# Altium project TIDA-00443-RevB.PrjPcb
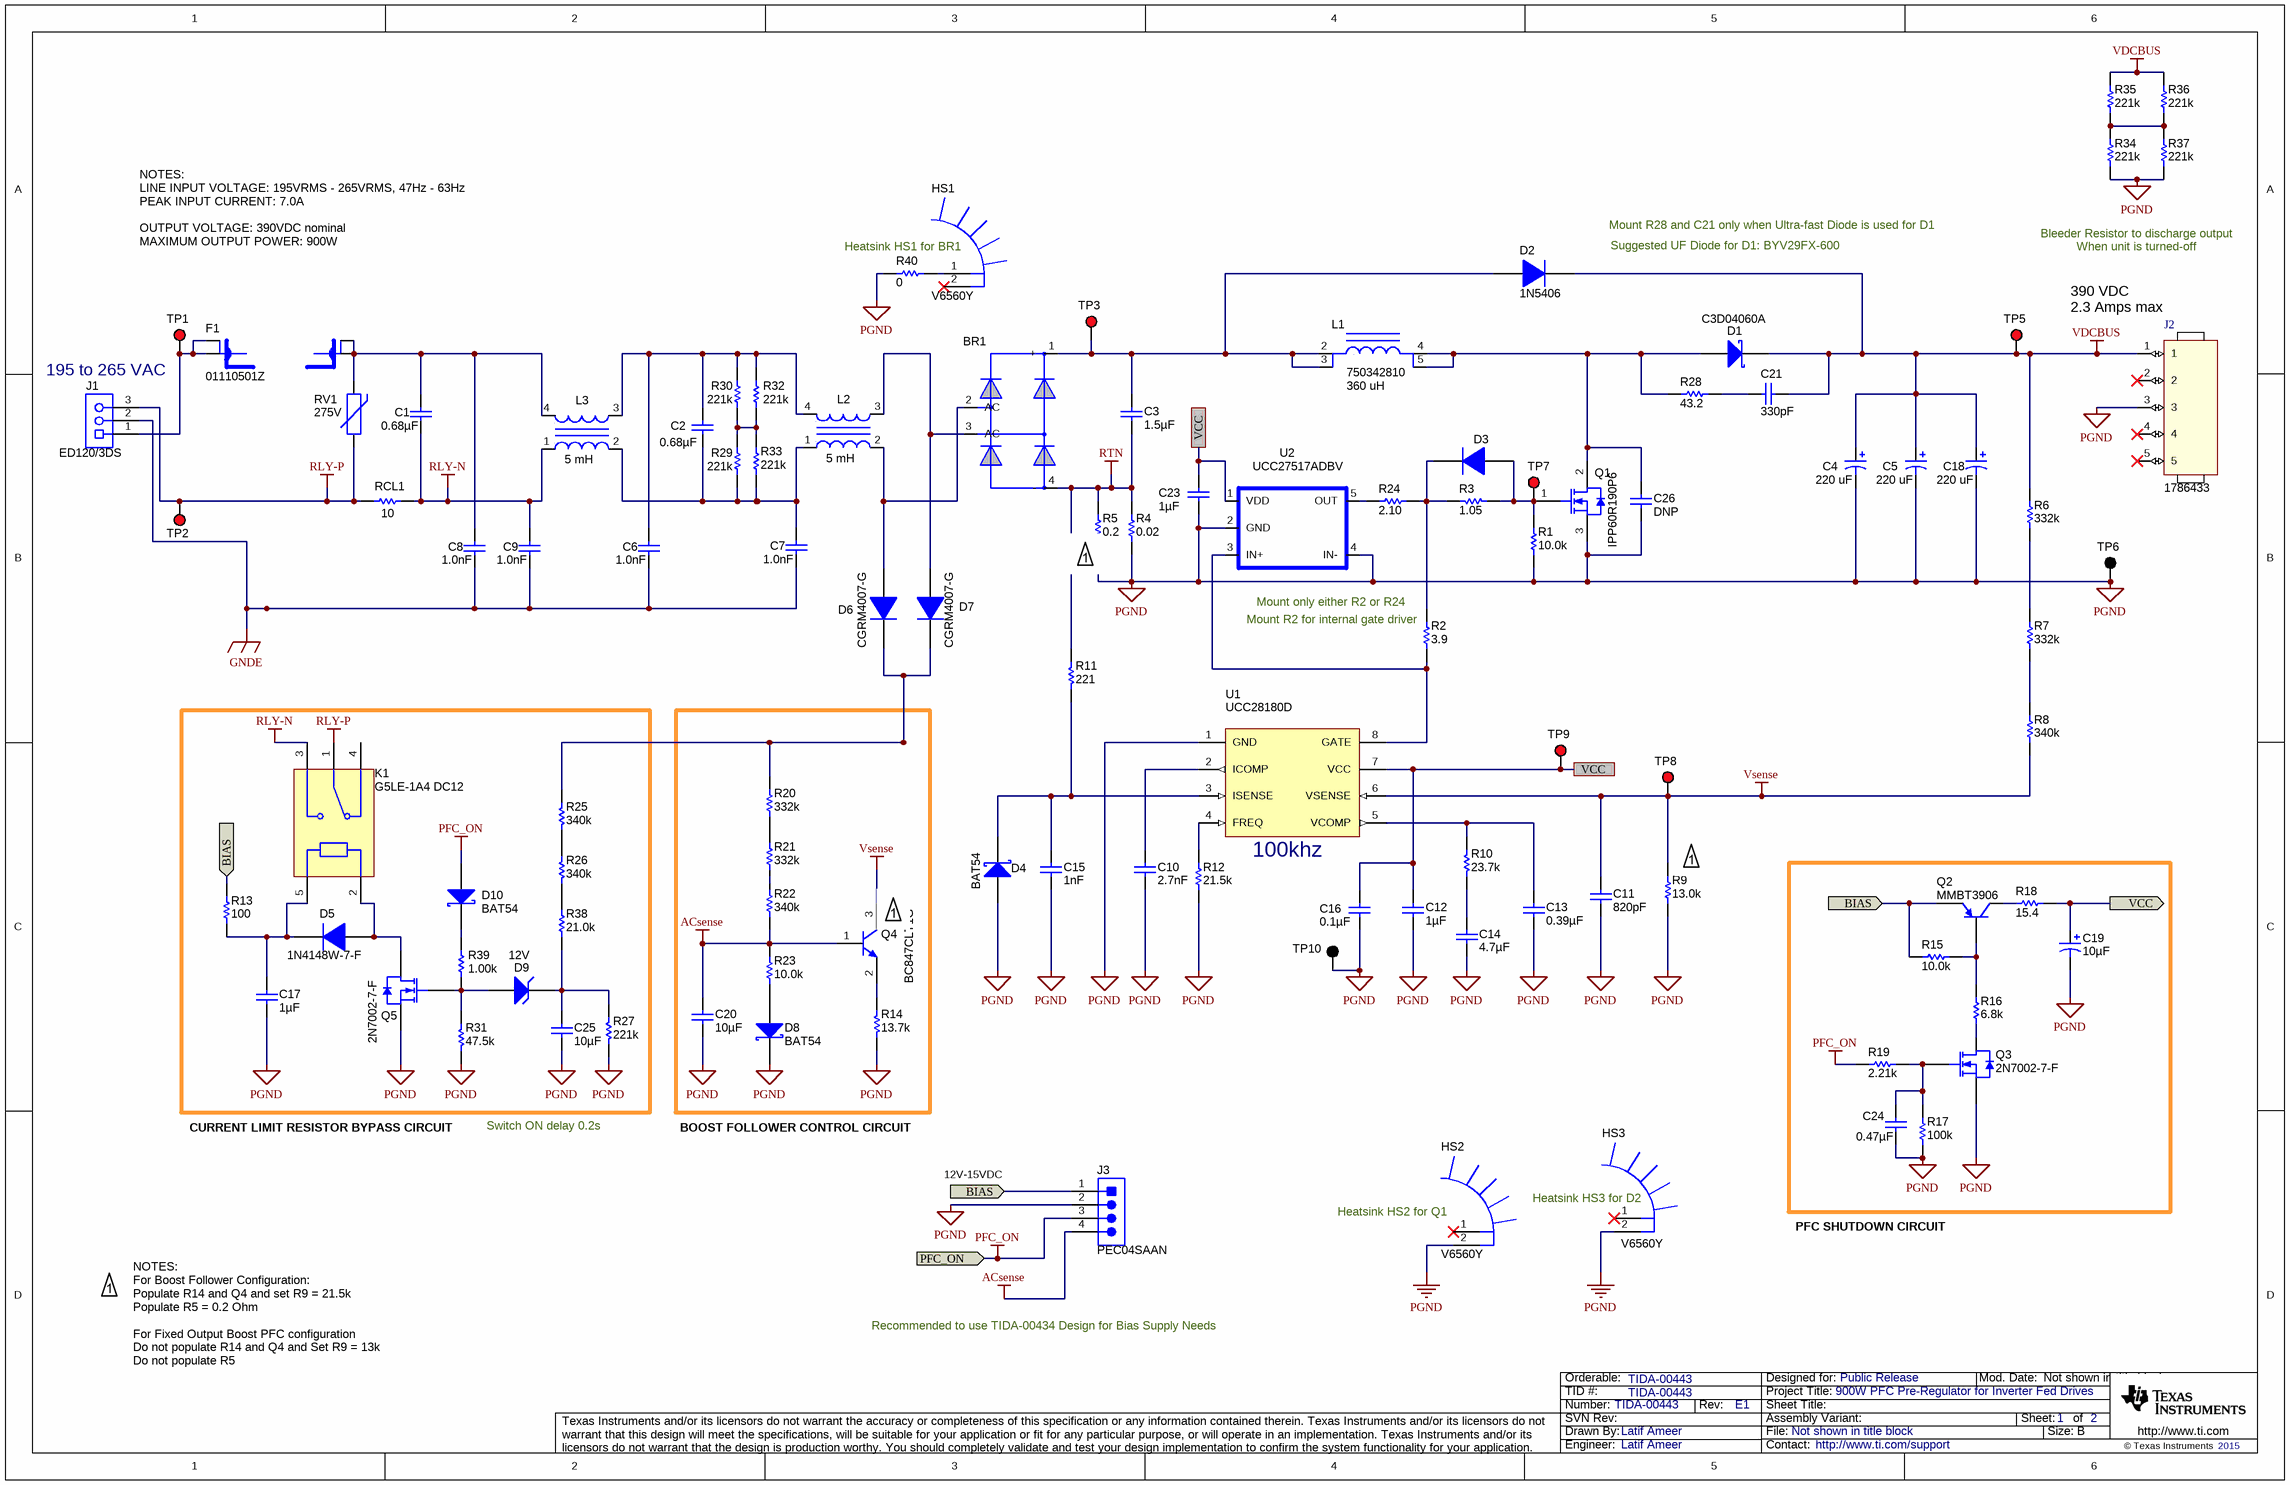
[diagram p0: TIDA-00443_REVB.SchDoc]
CopyrightYear: 2015; EVM_Orderable: TIDA-00443; PCB_Layout: Avinash; PCB_Rev: E2; PRJ_Customer: Public Release; PRJ_Engineer: Latif Ameer; PRJ_Number: TIDA-00443; PRJ_Title: 900W PFC Pre-Regulator for Inverter Fed Drives; SCH_Rev: E1; TechSupport: http://www.ti.com/support; TID: TIDA-00443
2 sheets, 124 parts. Net scope: flat (ports and power ports of the same name join across sheets).
Board file: TIDA-00443-RevB.PcbDoc
Sheets:
  TIDA-00443_REVB.SchDoc
  TID_Hardware.SchDoc

## Sheet TIDA-00443_REVB.SchDoc
size 431 x 279 mm; Date: 27-Mar-2015; ApprovedBy: Not shown in title block; CheckedBy: Salil Chellappan; Author: Latif Ameer; CompanyName: Texas Instruments India Pvt. Ltd; DrawnBy: Latif Ameer; Engineer: Latif Ameer; Organization: Not shown in title block; Address1: Not shown in title block; Address2: Not shown in title block; Address3: Not shown in title block; Address4: Not shown in title block; DocumentNumber: TIDA-00443-RevA; Revision: A; SheetNumber: 1; SheetTotal: 2; PageSetup: Record=PageOptions¦CenterHorizontal=True¦CenterVertical=True¦PrintScale=0.64¦XCorrection=1.00¦YCorrection=1.00¦PrintKind=0¦BorderSize=5000000¦LeftOffset=0¦BottomOffset=0¦Orientation=2¦PaperLength=1000¦PaperWidth=1000¦Scale=100¦PaperSource=15¦PrintQuality=-3¦MediaType=1¦DitherType=10¦PrintScaleMode=1¦PaperKind=Letter¦PaperIndex=1

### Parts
BR1  GBJ1508-BP  [BRIDGE-TSIL_PKG]  (value not drawn)
C1  ValueDisplayed: 0.68µF  [B32923_16.5mm_10.5]  (hidden comment: B32923C3684M)
C2  ValueDisplayed: 0.68µF  [B32923_16.5mm_10.5]  (hidden comment: B32923C3684M)
C3  ValueDisplayed: 1.5µF  [B32923_22mm]  (hidden comment: B32923C3155M)
C4  value 220 uF  [CAPPRD750W80D1800H5200]  (hidden comment: 450QXW220MEFC18X50)
C5  value 220 uF  [CAPPRD750W80D1800H5200]  (hidden comment: 450QXW220MEFC18X50)
C6  1.0nF  [CAPRD750W60D1050H1450]
C7  1.0nF  [CAPRD750W60D1050H1450]
C8  1.0nF  [CAPRD750W60D1050H1450]
C9  1.0nF  [CAPRD750W60D1050H1450]
C10  ValueDisplayed: 2.7nF  [0603]  (hidden comment: 06031C272JAT2A)
C11  ValueDisplayed: 820pF  [0603]  (hidden comment: C0603C821K5RACTU)
C12  ValueDisplayed: 1µF  [0603]  (hidden comment: C1608X7R1E105K080AB)
C13  ValueDisplayed: 0.39µF  [0603]  (hidden comment: C0603C394K4RACTU)
C14  ValueDisplayed: 4.7µF  [0603]  (hidden comment: GRM188R61C475KAAJ)
C15  ValueDisplayed: 1nF  [0603]  (hidden comment: 06031C102KAT2A)
C16  ValueDisplayed: 0.1µF  [0603]  (hidden comment: 06035C104KAT2A)
C17  ValueDisplayed: 1µF  [0603]  (hidden comment: C1608X7R1E105K080AB)
C18  value 220 uF  [CAPPRD750W80D1800H5200]  (hidden comment: 450QXW220MEFC18X50)
C19  ValueDisplayed: 10µF  [PW_500x700]  (hidden comment: UPW1V100MDD6)
C20  ValueDisplayed: 10µF  [0805_HV]  (hidden comment: C2012X5R1E106K125AB)
C21  ValueDisplayed: 330pF  [1206]  (hidden comment: GRM31A7U3A331JW31D)
C23  ValueDisplayed: 1µF  [0603]  (hidden comment: C1608X7R1E105K080AB)
C24  ValueDisplayed: 0.47µF  [0603]  (hidden comment: C0603C474K4RACTU)
C25  ValueDisplayed: 10µF  [1206]  (hidden comment: UMK316BBJ106ML-T)
C26  ValueDisplayed: DNP  [1206]  (hidden comment: GRM31A7U3A101JW31D)
D1  C3D04060A  [TO-220-F2]
D2  1N5406  [DO-201AD]
D3  MMDL914-TP  [sod-323]  (value not drawn)
D4  Alternate PartNumber: BAT54  [sod-323]  (hidden comment: BAT54HT1G)
D5  1N4148W-7-F  [SOD-123]
D6  CGRM4007-G  [MINI-SMA]
D7  CGRM4007-G  [MINI-SMA]
D8  Alternate PartNumber: BAT54  [sod-323]  (hidden comment: BAT54HT1G)
D9  value 12V  [sod-323]  (hidden comment: BZX384-C12,115)
D10  Alternate PartNumber: BAT54  [sod-323]  (hidden comment: BAT54HT1G)
F1  01110501Z  [LITTELFUSE_01110501Z]
HS1  V6560Y  [HS_ASS_0595]
HS2  V6560Y  [HS_ASS_0595]
HS3  V6560Y  [HS_ASS_0595]
J1  ED120/3DS  [CONN_ED120_3DS]
J2  1786433  [PHOENIX_1786433]
J3  PEC04SAAN  [SULLINS_PEC04SAAN]
K1  G5LE-1A4 DC12  [RELAY_G5LA-1]
L1  750342810  value 360 uH  [WE_750342810]
L2  5 mH  [IND_8113-RC]
L3  5 mH  [IND_8113-RC]
Q1  IPP60R190P6
Q2  MMBT3906  [SOT-23]
Q3  2N7002-7-F  [SOT-23]
Q4  BC847CLT1G  [SOT-23]
Q5  2N7002-7-F  [SOT-23]
R1  ValueDisplayed: 10.0k  [0603]  (hidden comment: CRCW060310K0FKEA)
R2  ValueDisplayed: 3.9  [1206]  (hidden comment: CRCW12063R90JNEA)
R3  ValueDisplayed: 1.05  [1206]  (hidden comment: CRCW12061R05FKEA)
R4  ValueDisplayed: 0.02  [2512]  (hidden comment: CRA2512-FZ-R020ELF)
R5  ValueDisplayed: 0.2  [2512]  (hidden comment: CRM2512-JW-201ELF)
R6  ValueDisplayed: 332k  [1206]  (hidden comment: CRCW1206332KFKEA)
R7  ValueDisplayed: 332k  [1206]  (hidden comment: CRCW1206332KFKEA)
R8  ValueDisplayed: 340k  [1206]  (hidden comment: CRCW1206340KFKEA)
R9  ValueDisplayed: 13.0k  [0603]  (hidden comment: CRCW060313K0FKEA)
R10  ValueDisplayed: 23.7k  [0603]  (hidden comment: CRCW060323K7FKEA)
R11  value 221  [0603M]  (hidden comment: CRCW0603221RFKEA)
R12  ValueDisplayed: 21.5k  [0603]  (hidden comment: CRCW060321K5FKEA)
R13  ValueDisplayed: 100  [1206]  (hidden comment: CRCW1206100RFKEA)
R14  ValueDisplayed: 13.7k  [0603]  (hidden comment: CRCW060313K7FKEA)
R15  value 10.0k  [0603]  (hidden comment: CRCW060310K0FKEA)
R16  ValueDisplayed: 6.8k  [0603]  (hidden comment: CRCW06036K80JNEA)
R17  ValueDisplayed: 100k  [0603]  (hidden comment: CRCW0603100KFKEA)
R18  ValueDisplayed: 15.4  [0603]  (hidden comment: CRCW060315R4FKEA)
R19  ValueDisplayed: 2.21k  [0603]  (hidden comment: CRCW06032K21FKEA)
R20  ValueDisplayed: 332k  [1206]  (hidden comment: CRCW1206332KFKEA)
R21  ValueDisplayed: 332k  [1206]  (hidden comment: CRCW1206332KFKEA)
R22  ValueDisplayed: 340k  [1206]  (hidden comment: CRCW1206340KFKEA)
R23  ValueDisplayed: 10.0k  [0603]  (hidden comment: CRCW060310K0FKEA)
R24  ValueDisplayed: 2.10  [1206]  (hidden comment: CRCW12062R10FKEA)
R25  ValueDisplayed: 340k  [1206]  (hidden comment: CRCW1206340KFKEA)
R26  ValueDisplayed: 340k  [1206]  (hidden comment: CRCW1206340KFKEA)
R27  ValueDisplayed: 221k  [0603]  (hidden comment: CRCW0603221KFKEA)
R28  ValueDisplayed: 43.2  [2512]  (hidden comment: CRM2512-FX-43R2ELF)
R29  ValueDisplayed: 221k  [1206]  (hidden comment: CRCW1206221KFKEA)
R30  ValueDisplayed: 221k  [1206]  (hidden comment: CRCW1206221KFKEA)
R31  ValueDisplayed: 47.5k  [0603]  (hidden comment: CRCW060347K5FKEA)
R32  ValueDisplayed: 221k  [1206]  (hidden comment: CRCW1206221KFKEA)
R33  ValueDisplayed: 221k  [1206]  (hidden comment: CRCW1206221KFKEA)
R34  ValueDisplayed: 221k  [1206]  (hidden comment: CRCW1206221KFKEA)
R35  ValueDisplayed: 221k  [1206]  (hidden comment: CRCW1206221KFKEA)
R36  ValueDisplayed: 221k  [1206]  (hidden comment: CRCW1206221KFKEA)
R37  ValueDisplayed: 221k  [1206]  (hidden comment: CRCW1206221KFKEA)
R38  ValueDisplayed: 21.0k  [1206]  (hidden comment: CRCW120621K0FKEA)
R39  ValueDisplayed: 1.00k  [0603]  (hidden comment: CRCW06031K00FKEA)
R40  ValueDisplayed: 0  [0805_HV]  (hidden comment: CRCW08050000Z0EA)
RCL1  ValueDisplayed: 10  [RESADV550W80L2600D750B]  (hidden comment: AC07000002009JAC00)
RV1  value 275V  [VAR_S10K275E2]  (hidden comment: S10K275E2)
TP1  5000  [Keystone5000]  (value not drawn)
TP2  5000  [Keystone5000]  (value not drawn)
TP3  5000  [Keystone5000]  (value not drawn)
TP5  5000  [Keystone5000]  (value not drawn)
TP6  5001  [Keystone5001]  (value not drawn)
TP7  5000  [Keystone5000]  (value not drawn)
TP8  5000  [Keystone5000]  (value not drawn)
TP9  5000  [Keystone5000]  (value not drawn)
TP10  5001  [Keystone5001]  (value not drawn)
U1  UCC28180D  [D0008A_N]
U2  UCC27517ADBV  [DBV0005A_N]

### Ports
BIAS, PFC_ON (in), VCC

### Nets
ACsense: C20.1 J3.4 Q4.1(B) R22.1 R23.1
GNDE: C6.2 C7.2 C8.2 C9.2 J1.2
PFC_ON: D10.2(A) J3.3 R19.1 ; port PFC_ON
PGND: C4.2(-) C5.2(-) C10.2 C11.2 C12.2 C13.1 C14.2 C15.1 C16.2 C17.2 C18.2(-) C19.2(-) C20.2 C23.2 C24.2 C25.2 C26.2 D4.2(A) D8.1(K) HS2.2 HS3.2 J2.3 J3.2 Q1.3(S) Q3.2(S) Q5.2(S) R1.2 R4.1 R5.1 R9.1 R12.2 R14.2 R17.1 R27.1 R31.1 R34.1 R37.1 R40.1 TP6.1 TP10.1 U1.1(GND) U2.2(GND) U2.4(IN-)
RLY-N: C1.2 C9.1 K1.3 L3.1 RCL1.2
RLY-P: J1.3 K1.1 RCL1.1 RV1.1 TP2.1
RTN: BR1.4(-) C3.2 R4.2 R5.2 R11.1
VDCBUS: C4.1(+) C5.1(+) C18.1(+) C21.1 D1.1(K) D2.1(K) J2.1 R6.2 R35.2 R36.2 TP5.1
Vsense: C11.1 Q4.3(C) R8.1 R9.2 TP8.1 U1.6(VSENSE)
BIAS: J3.1 Q2.2(E) R13.1 R15.1 ; port BIAS
VCC: C12.1 C16.1 C19.1(+) C23.1 R18.2 TP9.1 U1.7(VCC) U2.1(VDD) ; port VCC
NetBR1_1: BR1.1(+) C3.1 D2.2(A) L1.2 L1.3 TP3.1
NetBR1_2: BR1.2(AC) D6.2(A) L2.2
NetBR1_3: BR1.3(AC) D7.2(A) L2.3
NetC1_1: C1.1 C8.1 F1.3 F1.4 L3.4 RV1.2
NetC2_1: C2.1 C6.1 L2.4 L3.3 R30.1 R32.1
NetC2_2: C2.2 C7.1 L2.1 L3.2 R29.2 R33.2
NetC10_1: C10.1 U1.2(ICOMP)
NetC13_2: C13.2 R10.1 U1.5(VCOMP)
NetC14_1: C14.1 R10.2
NetC15_2: C15.2 D4.1(K) R11.2 U1.3(ISENSE)
NetC17_1: C17.1 D5.1(K) K1.5 R13.2
NetC21_2: C21.2 R28.2
NetC24_1: C24.1 Q3.1(G) R17.2 R19.2
NetC25_1: C25.1 D9.1(K) R27.2 R38.2
NetC26_1: C26.1 D1.2(A) L1.4 L1.5 Q1.2(D) R28.1
NetD3_1: D3.1(K) R2.2 R3.1 R24.1
NetD3_2: D3.2(A) Q1.1(G) R1.1 R3.2 TP7.1
NetD5_2: D5.2(A) K1.2 Q5.3(D)
NetD6_1: D6.1(K) D7.1(K) R20.2 R25.2
NetD8_2: D8.2(A) R23.2
NetD9_2: D9.2(A) Q5.1(G) R31.2 R39.2
NetD10_1: D10.1(K) R39.1
NetF1_1: F1.1 F1.2 J1.1 TP1.1
NetHS1_1: HS1.1 R40.2
NetQ2_1: Q2.1(B) R15.2 R16.2
NetQ2_3: Q2.3(C) R18.1
NetQ3_3: Q3.3(D) R16.1
NetQ4_2: Q4.2(E) R14.1
NetR2_1: R2.1 U1.8(GATE) U2.3(IN+)
NetR6_1: R6.1 R7.2
NetR7_1: R7.1 R8.2
NetR12_1: R12.1 U1.4(FREQ)
NetR20_1: R20.1 R21.1
NetR21_2: R21.2 R22.2
NetR24_2: R24.2 U2.5(OUT)
NetR25_1: R25.1 R26.1
NetR26_2: R26.2 R38.1
NetR29_1: R29.1 R30.2 R32.2 R33.1
NetR34_2: R34.2 R35.1 R36.1 R37.2

Not connected (* = marked no-connect by the designer): HS1 2*; HS2 1*; HS3 1*; J2 2* 4* 5*; K1 4

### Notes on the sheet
- Mount R28 and C21 only when Ultra-fast Diode is used for D1
- Bleeder Resistor to discharge output
- NOTES:
  LINE INPUT VOLTAGE: 195VRMS - 265VRMS, 47Hz - 63Hz
  PEAK INPUT CURRENT: 7.0A
  OUTPUT VOLTAGE: 390VDC nominal
  MAXIMUM OUTPUT POWER: 900W
- Heatsink HS1 for BR1
- Suggested UF Diode for D1: BYV29FX-600
- When unit is turned-off
- 390 VDC
  2.3 Amps max
- 195 to 265 VAC
- (near R2) Mount only either R2 or R24
- (near R2) Mount R2 for internal gate driver
- (near U1) 100khz
- CURRENT LIMIT RESISTOR BYPASS CIRCUIT
- Switch ON delay 0.2s
- BOOST FOLLOWER CONTROL CIRCUIT
- 12V-15VDC
- (near HS2) Heatsink HS2 for Q1
- (near HS3) Heatsink HS3 for D2
- PFC SHUTDOWN CIRCUIT
- NOTES:
  For Boost Follower Configuration:
  Populate R14 and Q4 and set R9 = 21.5k
  Populate R5 = 0.2 Ohm
  For Fixed Output Boost PFC configuration
  Do not populate R14 and Q4 and Set R9 = 13k
  Do not populate R5
- Recommended to use TIDA-00434 Design for Bias Supply Needs

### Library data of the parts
BR1 = D-BRIDGE_GBJ_15A_SERIES: Diode, Bridge Rectifier, GPP 15A 800V GBJ; Manufacturer: Micro Commercial Co; Area: 25452
C1 C2 = B32923C3684M: CAP, Film, 0.68 µF, 630 V, +/- 20%, TH; Manufacturer: EPCOS Inc; Polarized: N; CompType: Capacitor; Value: 0.68uF; U/M: EA; Cap_F: 0.00000068; Tolerance_%: 20; Value1: Unknown; VDC_V: 630; Value2: 630V; TaMax_C: 110
C3 = B32923C3155M: CAP, Film, 1.5 µF, 630 V, +/- 20%, 0.017 ohm, TH; Manufacturer: EPCOS Inc; Polarized: N; CompType: Capacitor; Value: 1.5uF; U/M: EA; Cap_F: 0.0000015; Tolerance_%: 20; VDC_V: 630; Value2: 630V; ESR_ohm: 0.017; IRMS_A: 0.146; TaMax_C: 110
C4 C5 C18 = 450QXW220MEFC18X50: CAP, ALUMINIUM, RADIAL, 220 uF, 450 V, 20%, TH; Manufacturer: RUBYCON; CompType: Aluminium Capacitor; SymbolCreator: x0199378
C6-C9 = CS11-E2GA222MYNS: CAP CER 1000PF 300VAC 20% RADIAL DISC 7mm Dia; PartNumber: CS65ZU2GA102MYNKA; Manufacturer: TDK; Polarized: N; CompType: Capacitor; U/M: EA; Cap_F: 0.0000000010; Tolerance_%: 20; Value1: Unknown; VDC_V: 300; Value2: 300V; TempCo: E; TaMin_C: -25; TaMax_C: 105; Cap_Case: Disc, 10.5x7mm
C10 = 06031C272JAT2A: CAP, CERM, 2700 pF, 100 V, +/- 5%, X7R, 0603; Manufacturer: AVX; Value: 2700pF; Polarized: N; CompType: Capacitor; U/M: EA; Cap_F: 0.0000000027; Tolerance_%: 5; ESR_ohm: 0.174; Value1: 0.174 ohm; VDC_V: 100; Value2: 100V; TaMin_C: -55; TaMax_C: 125
C11 = C0603C821K5RACTU: CAP, CERM, 820 pF, 50 V, +/- 10%, X7R, 0603; Manufacturer: Kemet; Value: 820pF; Polarized: N; CompType: Capacitor; U/M: EA; Cap_F: 0.00000000082; Tolerance_%: 10; Value1: Unknown; VDC_V: 50; Value2: 50V; TaMin_C: -55; TaMax_C: 125
C12 C17 C23 = C1608X7R1E105K080AB: CAP, CERM, 1 µF, 25 V, +/- 10%, X7R, 0603; Manufacturer: TDK; Polarized: N; CompType: Capacitor; Value: 1uF; U/M: EA; Cap_F: 0.000001; Tolerance_%: 10; Value1: Unknown; VDC_V: 25; Value2: 25V; TaMin_C: -55; TaMax_C: 125
C13 = C0603C394K4RACTU: CAP, CERM, 0.39 µF, 16 V, +/- 10%, X7R, 0603; Manufacturer: Kemet; Value: 0.39uF; Polarized: N; CompType: Capacitor; U/M: EA; Cap_F: 0.00000039; Tolerance_%: 10; Value1: Unknown; VDC_V: 16; Value2: 16V; TaMin_C: -55; TaMax_C: 125
C14 = GRM188R61C475KAAJ: CAP, CERM, 4.7 µF, 16 V, +/- 10%, X5R, 0603; Manufacturer: MuRata; Value: 4.7uF; Polarized: N; CompType: Capacitor; U/M: EA; Cap_F: 0.0000047; Tolerance_%: 10; Value1: Unknown; VDC_V: 16; Value2: 16V; TaMin_C: -55; TaMax_C: 85
C15 = 06031C102KAT2A: CAP, CERM, 1000 pF, 100 V, +/- 10%, X7R, 0603; Manufacturer: AVX; Value: 1000pF; Polarized: N; CompType: Capacitor; U/M: EA; Cap_F: 0.000000001; Tolerance_%: 10; ESR_ohm: 0.276; Value1: 0.276 ohm; VDC_V: 100; Value2: 100V; TaMin_C: -55; TaMax_C: 125
C16 = 06035C104KAT2A: CAP, CERM, 0.1 µF, 50 V, +/- 10%, X7R, 0603; Manufacturer: AVX; Value: 0.1uF; Polarized: N; CompType: Capacitor; U/M: EA; Cap_F: 0.0000001; Tolerance_%: 10; Value1: Unknown; VDC_V: 50; Value2: 50V; TaMin_C: -55; TaMax_C: 125
C19 = UPW1V100MDD6: CAP, AL, 10uF, 35V, +/-20%, 0.95 ohm, TH; Manufacturer: Nichicon; Polarized: Y; CompType: Capacitor; U/M: EA; Cap_F: 0.00001; Tolerance_%: 20; VDC_V: 35; ESR_Ohm: 0.95; IRMS_A: 0.12; TaMin_C: -55; TaMax_C: 105; Cap_Case: 5x7
C20 = C2012X5R1E106K125AB: CAP, CERM, 10 µF, 25 V, +/- 10%, X5R, 0805; Manufacturer: TDK; Polarized: N; CompType: Capacitor; Value: 10uF; U/M: EA; Cap_F: 0.00001; Tolerance_%: 10; Value1: Unknown; VDC_V: 25; Value2: 25V; TaMin_C: -55; TaMax_C: 85; Cap_Case: 0805
C21 = GRM31A7U3A331JW31D: CAP, CERM, 330 pF, 1000 V, +/- 5%, U2J, 1206; Manufacturer: MuRata; Polarized: N; CompType: Capacitor; Value: 330pF; U/M: EA; Cap_F: 0.00000000033; Tolerance_%: 5; Value1: Unknown; VDC_V: 1000; Value2: 1000V; TaMin_C: -55; TaMax_C: 125
C24 = C0603C474K4RACTU: CAP, CERM, 0.47 µF, 16 V, +/- 10%, X7R, 0603; Manufacturer: Kemet; Value: 0.47uF; Polarized: N; CompType: Capacitor; U/M: EA; Cap_F: 0.00000047; Tolerance_%: 10; Value1: Unknown; VDC_V: 16; Value2: 16V; TaMin_C: -55; TaMax_C: 125
C25 = GRM319R61H475KA12: CAP CER 10UF 50V 20% X5R 1206; Manufacturer: Taiyo Yuden; Polarized: N; CompType: Capacitor; U/M: EA; Cap_F: 0.0000010; Tolerance_%: 20; Value1: Unknown; VDC_V: 50; TaMin_C: -55; TaMax_C: 85
C26 = GRM31A7U3A101JW31D: CAP, CERM, 100 pF, 1000 V, +/- 5%, U2J, 1206; Manufacturer: MuRata; Polarized: N; CompType: Capacitor; Value: 100pF; U/M: EA; Cap_F: 0.0000000001; Tolerance_%: 5; Value1: Unknown; VDC_V: 1000; Value2: 1000V; TaMin_C: -55; TaMax_C: 125
D1 = C3D04060A: Diode, Schottky, 600 V, 4 A, TH; Manufacturer: Cree; Value: 600V; U/M: EA; Vf_V: 1.8; Value1: 4A; Value2: 1.8V; Io_A: 4; Vr_V: 600; TJmax_C: 175; RJC_CperW: 11.5
D2 = 1N5406: Diode, Switching-Bridge, 600 V, 3 A, TH; Manufacturer: Vishay-Semiconductor; U/M: EA; Vf_V: 1.2; Value: 600V; Value1: 3A; Value2: 1.2V; Io_A: 3; Vr_V: 600; TJmax_C: 150
D3 = MMDL914-TP: Diode, Switching, 100 V, 0.2 A, SOD-323; Manufacturer: Micro Commercial Components; Value: 100V; U/M: EA; Vf_V: 1; Value1: 0.2A; Value2: 1V; Io_A: 0.2; Vr_V: 100; TJmax_C: 150; RJC_CperW: 635
D4 D8 D10 = BAT54HT1G: Diode, Schottky, 30V, 0.2A, SOD-323; Manufacturer: Fairchild; U/M: EA; Vf_V: 0.35; Value2: 0.35V; Io_A: 0.2; Vr_V: 30
D5 = 1N4148W-7-F: Diode, Ultrafast, 100V, 0.15A, SOD-123; Manufacturer: Diodes Inc.; U/M: EA; Vf_V: 1.25; Value2: 1.25V; Io_A: 0.15; Vr_V: 100; TJmax_C: 150
D6 D7 = CGRM4007-G: Diode, P-N, 1000 V, 1 A, 3.9x1.7x1.8mm; Manufacturer: Comchip Technology; U/M: EA; Vf_V: 1.1; Value: 1000V; Value1: 1A; Value2: 1.1V; Io_A: 1; Vr_V: 1000; TJmax_C: 150
D9 = BZX384-C12,115: Diode, Zener, 12V, 300mW, SOD-323; Manufacturer: NXP Semiconductor; SymbolCreator: a0412235; U/M: EA; Power_W: 0.3; Vz_V: 12; Value1: 0.3W; RJA_CperW: 415
F1 = 01110501Z: FUSE CLIP, CARTRIDGE, 250V, 10A, PCB; Manufacturer: LITTELFUSE; SymbolCreator: x0199378
HS1-HS3 = 531002B02500G: HEATSINK ALUM Black Anodized, Board Mount; Manufacturer: Assmann; SymbolCreator: a0799628
J1 = ED120/3DS: TERMINAL BLOCK 5.08MM VERT 3POS, TH; Manufacturer: On-Shore Technology; SymbolCreator: a0412235; U/M: EA
J2 = 1786433: TERM BLOCK HDR 5POS R/A 5.08MM; Manufacturer: PHOENIX CONTACT; SymbolCreator: x0199378; CompType: Terminal Block
J3 = PEC04SAAN: Header, 100mil, 4x1, Tin, TH; Manufacturer: Sullins Connector Solutions; SymbolCreator: a0412235; U/M: EA
K1 = G5LA-14 DC5: Relay, SPST-NO (1 Form A), 10A, 12 VDC, TH; Manufacturer: Omron Electronic Components; SymbolCreator: a0411947; Coil Current: 33 mA; Coil Power: 360 mW; Coil Resistance: 360 ohms; Coil Type: Non Latching; Coil Voltage: 12 VDC; Turn Off Voltage (Min): 1.2 VDC; Turn On Voltage (Max): 9 VDC; Time Operate (s): 0.01; Time Release (s): 0.005
L1 = 750342810: INDUCTOR, 360 uH, 8.3 A, 10%, TH; Manufacturer: Wurth Electronik; SymbolCreator: x0199378
L2 L3 = 8113-RC: INDUCTOR, CHOKE, COMMON MODE, 5 mH, 8.9 A, 22 mOHM, TH; Manufacturer: Bourns Inc; SymbolCreator: x0199378
Q1 = IPP60R190P6: MOSFET, N-CH, 600 V, 20.2 A, TO-220; Manufacturer: Infineon Technologies; Value: 600 V; SymbolCreator: x0199378
Q2 = MMBT3906, Fairchild Semiconductor: Transistor, PNP, 40V, 0.2A, SOT-23; CompType: BJT; PNP: 1; NPN: 0; Vceo_V: 40; Vcesat1_V: 0.25; Value: 0.25V; IcRated_A: 0.2; HfeMax: 300; TaMin_C: -55; TaMax_C: 150; U/M: EA
Q3 Q5 = 2N7002-7-F: MOSFET, N-CH, 60V, 0.17A, SOT-23; Manufacturer: Diodes Inc.; Alternate Manufacturer: None; U/M: EA; ChType: N; VdsMax_V: 60; Value1: 7.5 ohm; Rdson45_Ohm: 7.5; Value2: 223 nC; QgTyp_nC: 223; Vgs_V: 20; IdsMax_A: 0.17
Q4 = BC847CLT1G, ON Semiconductor: Transistor, NPN, 45 V, 0.1 A, SOT-23; CompType: BJT; PNP: 0; NPN: 1; Vceo_V: 45; Vcesat1_V: 0.7; Value: 45 V; IcRated_A: 0.1; Value1: 0.1 A; HfeMax: 800; TaMin_C: -55; TaMax_C: 150; U/M: EA
R1 R23 = CRCW060310K0FKEA: RES, 10.0 k, 1%, 0.1 W, 0603; Manufacturer: Vishay-Dale; CompType: Resistor; Value: 10.0k; Res_ohm: 10000; Value_Code: 10k0; Tolerance_%: 1; Power_W: 0.1; Value2: 0.1W; VDC_V: 75; TempCo: 100 ppm/C; EIA_Code: E96; U/M: EA
R2 = CRCW12063R90JNEA: RES, 3.9, 5%, 0.25 W, 1206; Manufacturer: Vishay-Dale; Value: 3.9; CompType: Resistor; Value_Code: 3R90; Tolerance_%: 5; Power_W: 0.25; Value2: 0.25W; VDC_V: 200; TempCo: 200 ppm/C; EIA_Code: E24; U/M: EA
R3 = CRCW12061R05FKEA: RES, 1.05, 1%, 0.25 W, 1206; Manufacturer: Vishay-Dale; Value: 1.05; CompType: Resistor; Value_Code: 1R05; Tolerance_%: 1; Power_W: 0.25; Value2: 0.25W; VDC_V: 200; TempCo: 100 ppm/C; EIA_Code: E96; U/M: EA
R4 = CRA2512-FZ-R020ELF: RES, 0.02, 1%, 3 W, 2512; Manufacturer: Bourns; Value: 0.02; CompType: Resistor; Value_Code: R020; Tolerance_%: 1; Power_W: 3; Value2: 3W; TempCo: 75 ppm/C; EIA_Code: E96; U/M: EA
R5 = CSRN2512FKR200: RES, 0.2, 1%, 2 W, 2512; Manufacturer: Bourns; Value: 0.2; CompType: Resistor; Value_Code: R200; Tolerance_%: 1; Power_W: 2; Value2: 2W; TempCo: 200 ppm/C; EIA_Code: E96; U/M: EA
R6 R7 R20 R21 = CRCW1206332KFKEA: RES, 332 k, 1%, 0.25 W, 1206; Manufacturer: Vishay-Dale; Value: 332k; CompType: Resistor; Res_ohm: 332000; Tolerance_%: 1; Power_W: 0.25; Value2: 0.25W; VDC_V: 200; TempCo: 100 ppm/C; EIA_Code: E96; U/M: EA
R8 R22 R25 R26 = CRCW1206340KFKEA: RES, 340 k, 1%, 0.25 W, 1206; Manufacturer: Vishay-Dale; Value: 340k; CompType: Resistor; Res_ohm: 340000; Tolerance_%: 1; Power_W: 0.25; Value2: 0.25W; VDC_V: 200; TempCo: 100 ppm/C; EIA_Code: E96; U/M: EA
R9 = CRCW060313K0FKEA: RES, 13.0 k, 1%, 0.1 W, 0603; Manufacturer: Vishay-Dale; Value: 13.0k; CompType: Resistor; Res_ohm: 13000; Value_Code: 13k0; Tolerance_%: 1; Power_W: 0.1; Value2: 0.1W; VDC_V: 75; TempCo: 100 ppm/C; EIA_Code: E96; U/M: EA
R10 = CRCW060323K7FKEA: RES, 23.7 k, 1%, 0.1 W, 0603; Manufacturer: Vishay-Dale; Value: 23.7k; CompType: Resistor; Res_ohm: 23700; Value_Code: 23k7; Tolerance_%: 1; Power_W: 0.1; Value2: 0.1W; VDC_V: 75; TempCo: 100 ppm/C; EIA_Code: E96; U/M: EA
R11 = CRCW0603221RFKEA: RES, 221 ohm, 1%, 0.1W, 0603; Manufacturer: Vishay-Dale; CompType: Resistor; Value_Code: 221R; Tolerance_%: 1; Power_W: 0.1; VDC_V: 75; TempCo: 100 ppm/C; EIA_Code: E96; U/M: EA
R12 = CRCW060321K5FKEA: RES, 21.5 k, 1%, 0.1 W, 0603; Manufacturer: Vishay-Dale; Value: 21.5k; CompType: Resistor; Res_ohm: 21500; Value_Code: 21k5; Tolerance_%: 1; Power_W: 0.1; Value2: 0.1W; VDC_V: 75; TempCo: 100 ppm/C; EIA_Code: E96; U/M: EA
R13 = CRCW1206100RFKEA: RES, 100, 1%, 0.25 W, 1206; Manufacturer: Vishay-Dale; Value: 100; CompType: Resistor; Value_Code: 100R; Tolerance_%: 1; Power_W: 0.25; Value2: 0.25W; VDC_V: 200; TempCo: 100 ppm/C; EIA_Code: E96; U/M: EA
R14 = CRCW060313K7FKEA: RES, 13.7 k, 1%, 0.1 W, 0603; Manufacturer: Vishay-Dale; Value: 13.7k; CompType: Resistor; Res_ohm: 13700; Value_Code: 13k7; Tolerance_%: 1; Power_W: 0.1; Value2: 0.1W; VDC_V: 75; TempCo: 100 ppm/C; EIA_Code: E96; U/M: EA
R15 = CRCW060310K0FKEA: RES, 10.0k ohm, 1%, 0.1W, 0603; Manufacturer: Vishay-Dale; CompType: Resistor; Res_ohm: 10000; Value_Code: 10k0; Tolerance_%: 1; Power_W: 0.1; VDC_V: 75; TempCo: 100 ppm/C; EIA_Code: E96; U/M: EA
R16 = CRCW06036K80JNEA: RES, 6.8 k, 5%, 0.1 W, 0603; Manufacturer: Vishay-Dale; CompType: Resistor; Value: 6.8k; Res_ohm: 6800; Value_Code: 6k80; Tolerance_%: 5; Power_W: 0.1; Value2: 0.1W; VDC_V: 75; TempCo: 200 ppm/C; EIA_Code: E24; U/M: EA
R17 = CRCW0603100KFKEA: RES, 100 k, 1%, 0.1 W, 0603; Manufacturer: Vishay-Dale; CompType: Resistor; Value: 100k; Res_ohm: 100000; Tolerance_%: 1; Power_W: 0.1; Value2: 0.1W; VDC_V: 75; TempCo: 100 ppm/C; EIA_Code: E96; U/M: EA
R18 = CRCW060315R4FKEA: RES, 15.4, 1%, 0.1 W, 0603; Manufacturer: Vishay-Dale; CompType: Resistor; Value: 15.4; Value_Code: 15R4; Tolerance_%: 1; Power_W: 0.1; Value2: 0.1W; VDC_V: 75; TempCo: 100 ppm/C; EIA_Code: E96; U/M: EA
R19 = CRCW06032K21FKEA: RES, 2.21 k, 1%, 0.1 W, 0603; Manufacturer: Vishay-Dale; CompType: Resistor; Value: 2.21k; Res_ohm: 2210; Value_Code: 2k21; Tolerance_%: 1; Power_W: 0.1; Value2: 0.1W; VDC_V: 75; TempCo: 100 ppm/C; EIA_Code: E96; U/M: EA
R24 = CRCW12062R10FKEA: RES, 2.10, 1%, 0.25 W, 1206; Manufacturer: Vishay-Dale; Value: 2.10; CompType: Resistor; Res_ohm: 2.1; Value_Code: 2R10; Tolerance_%: 1; Power_W: 0.25; Value2: 0.25W; VDC_V: 200; TempCo: 100 ppm/C; EIA_Code: E96; U/M: EA
R27 = CRCW0603221KFKEA: RES, 221 k, 1%, 0.1 W, 0603; Manufacturer: Vishay-Dale; CompType: Resistor; Value: 221k; Res_ohm: 221000; Tolerance_%: 1; Power_W: 0.1; Value2: 0.1W; VDC_V: 75; TempCo: 100 ppm/C; EIA_Code: E96; U/M: EA
R28 = CRCW2512100RFKEG: RES, 100, 1%, 1 W, 2512; Manufacturer: Vishay-Dale; CompType: Resistor; Value: 100; Value_Code: 100R; Tolerance_%: 1; Value2: 2W; VDC_V: 500; TempCo: 100 ppm/C; EIA_Code: E96; U/M: EA
R29 R30 R32-R37 = CRCW1206221KFKEA: RES, 221 k, 1%, 0.25 W, 1206; Manufacturer: Vishay-Dale; Value: 221k; CompType: Resistor; Res_ohm: 221000; Tolerance_%: 1; Power_W: 0.25; Value2: 0.25W; VDC_V: 200; TempCo: 100 ppm/C; EIA_Code: E96; U/M: EA
R31 = CRCW060347K5FKEA: RES, 47.5 k, 1%, 0.1 W, 0603; Manufacturer: Vishay-Dale; CompType: Resistor; Value: 47.5k; Res_ohm: 47500; Value_Code: 47k5; Tolerance_%: 1; Power_W: 0.1; Value2: 0.1W; VDC_V: 75; TempCo: 100 ppm/C; EIA_Code: E96; U/M: EA
R38 = CRCW120621K0FKEA: RES, 21.0 k, 1%, 0.25 W, 1206; Manufacturer: Vishay-Dale; Value: 21.0k; CompType: Resistor; Res_ohm: 21000; Value_Code: 21k0; Tolerance_%: 1; Power_W: 0.25; Value2: 0.25W; VDC_V: 200; TempCo: 100 ppm/C; EIA_Code: E96; U/M: EA
R39 = CRCW06031K00FKEA: RES, 1.00 k, 1%, 0.1 W, 0603; Manufacturer: Vishay-Dale; CompType: Resistor; Value: 1.00k; Res_ohm: 1000; Value_Code: 1k00; Tolerance_%: 1; Power_W: 0.1; Value2: 0.1W; VDC_V: 75; TempCo: 100 ppm/C; EIA_Code: E96; U/M: EA
R40 = CRCW08050000Z0EA: RES, 0, 5%, 0.125 W, 0805; Manufacturer: Vishay-Dale; CompType: Resistor; Value: 0; Value_Code: 0000; Tolerance_%: 5; Power_W: 0.125; Value2: 0.125W; VDC_V: 150; TempCo: 200 ppm/C; EIA_Code: E24; U/M: EA
RCL1 = AC07000002009JAC00: RES 10 OHM 7W 5% AXIAL; Manufacturer: Vishay-Dale; CompType: Resistor; Value: 10; Value_Code: 10R0; Tolerance_%: 5; Power_W: 7; TempCo: 80 ppm/C; EIA_Code: E24; U/M: EA
RV1 = S10K275E2: Varistor 275V RMS 10MM Radial, TH; Manufacturer: EPCOS Inc; SymbolCreator: a0412235
TP1-TP3 TP5 TP7-TP9 = 5000: Test Point, Miniature, Red, TH; Manufacturer: Keystone; CompType: Test Point Loop; U/M: EA
TP6 TP10 = 5001: Test Point, Miniature, Black, TH; Manufacturer: Keystone; CompType: Test Point Loop; U/M: EA
U1 = UCC28180D: 8-PIN CONTINUOUS CONDUCTION MODE (CCM) PFC CONTROLLER, D0008A; Alternate Manufacturer: None; Manufacturer: Texas Instruments; SymbolCreator: a0411947; CompType: IC; U/M: EA
U2 = UCC27517DBV: IC, 4A Single Channel High-Speed Low-Side Gate Drivers; Manufacturer: TI; Alternate Manufacturer: None; Area: 23360

## Sheet TID_Hardware.SchDoc
size 431 x 279 mm; Date: Not shown in title block; ApprovedBy: Not shown in title block; CheckedBy: Not shown in title block; Author: Not shown in title block; CompanyName: Not shown in title block; DrawnBy: Latif Ameer; Engineer: Not shown in title block; Organization: Not shown in title block; Address1: Not shown in title block; Address2: Not shown in title block; Address3: Not shown in title block; Address4: Not shown in title block; DocumentNumber: 1; Revision: Use project parameter SCH_Rev; SheetNumber: 2; SheetTotal: 2; PageSetup: Record=PageOptions|CenterHorizontal=True|CenterVertical=True|PrintScale=1.00|XCorrection=1.00|YCorrection=1.00|PrintKind=0|BorderSize=5000000|LeftOffset=0|BottomOffset=0|Orientation=2|PaperLength=1000|PaperWidth=1000|Scale=100|PaperSource=15|PrintQuality=600|MediaType=1|DitherType=10|PaperKind=Letter|PrintScaleMode=1
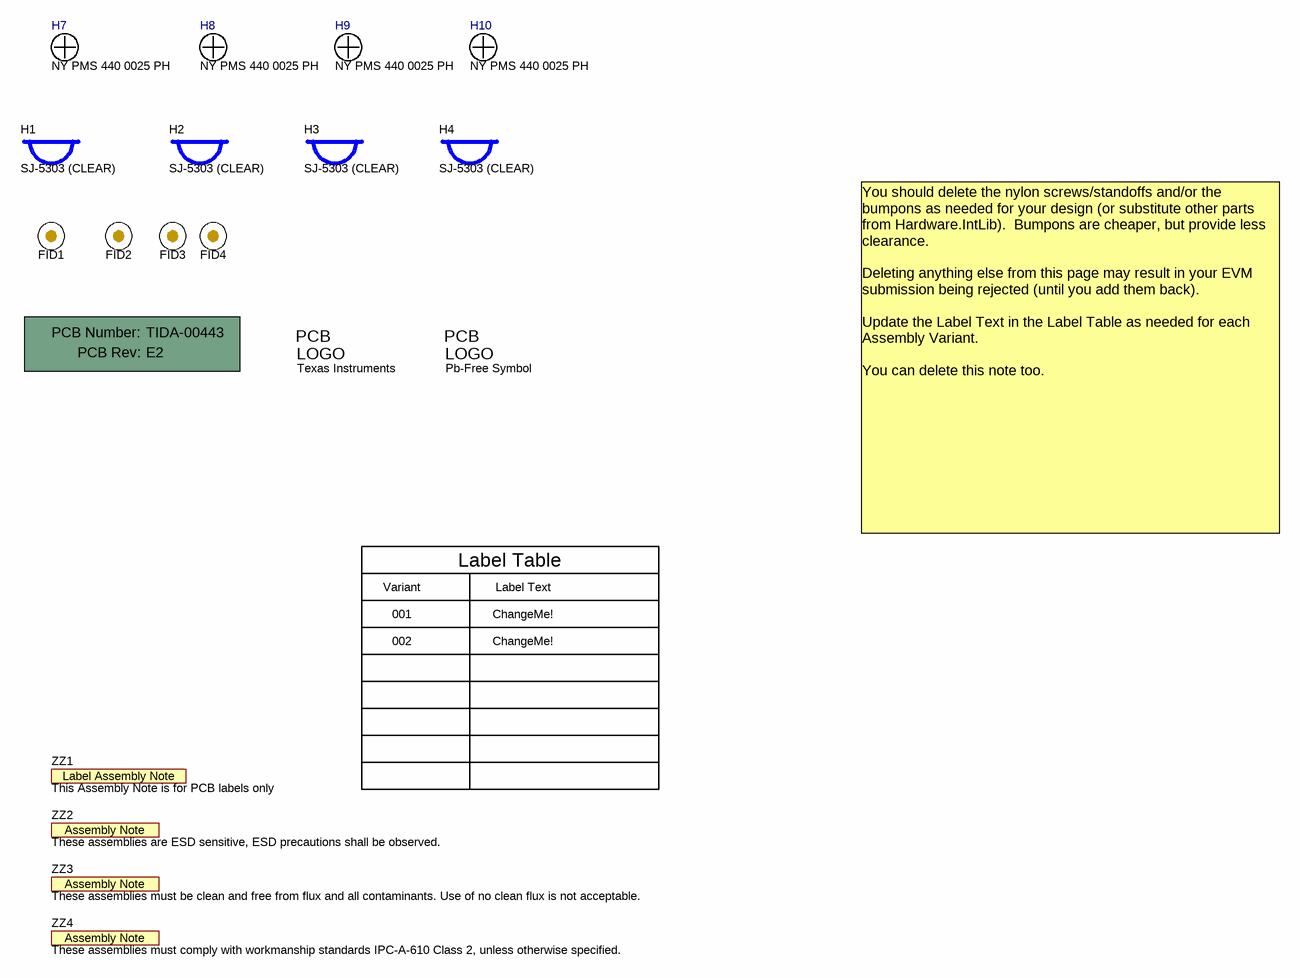
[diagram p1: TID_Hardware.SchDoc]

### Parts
!PCB  Printed Circuit Board  (value not drawn)  (mechanical)
FID1  Fiducial  [Fiducial10-20]  (value not drawn)
FID2  Fiducial  [Fiducial10-20]  (value not drawn)
FID3  Fiducial  [Fiducial10-20]  (value not drawn)
FID4  Fiducial  [Fiducial10-20]  (value not drawn)
H1  SJ-5303 (CLEAR)  [Bumpon_SJ5003Transparent]
H2  SJ-5303 (CLEAR)  [Bumpon_SJ5003Transparent]
H3  SJ-5303 (CLEAR)  [Bumpon_SJ5003Transparent]
H4  SJ-5303 (CLEAR)  [Bumpon_SJ5003Transparent]
H7  NY PMS 440 0025 PH  [NY PMS 440 0025 PH]
H8  NY PMS 440 0025 PH  [NY PMS 440 0025 PH]
H9  NY PMS 440 0025 PH  [NY PMS 440 0025 PH]
H10  NY PMS 440 0025 PH  [NY PMS 440 0025 PH]
Logo1  Texas Instruments  [TI_Stacked_Overlay_Small]  (no BOM)
Logo2  Pb-Free Symbol  [Pb-Free_Overlay_Small]  (no BOM)
ZZ1  This Assembly Note is for PCB labels only  [AssemblyNoteLabel]  (no BOM)
ZZ2  These assemblies are ESD sensitive, ESD precautions shall be observed.  [AssemblyNote]  (no BOM)
ZZ3  These assemblies must be clean and free from flux and all contaminants. Use of no clean flux is not acceptable.  [AssemblyNote]  (no BOM)
ZZ4  These assemblies must comply with workmanship standards IPC-A-610 Class 2, unless otherwise specified.  [AssemblyNote]  (no BOM)

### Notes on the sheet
- Variant
- Label Table
- Label Text
- You should delete the nylon screws/standoffs and/or the bumpons as needed for your design (or substitute other parts from Hardware.IntLib).  Bumpons are cheaper, but provide less clearance.
  Deleting anything else from this page may result in your EVM submission being rejected (until you add them back).
  Update the Label Text in the Label Table as needed for each Assembly Variant.
  You can delete this note too.
- 001
- 002
- ChangeMe!

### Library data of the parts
!PCB = PCB: Manufacturer: Any; PartNumber: TIDA-00443; SymbolCreator: a0412235
FID1-FID4 = Fiducial: Fiducial mark.  There is nothing to buy or mount.; SymbolCreator: codlsc
H1-H4 = SJ-5303 (CLEAR): Bumpon, Hemisphere, 0.44 X 0.20, Clear; Manufacturer: 3M; SymbolCreator: a0412235
H7-H10 = NY PMS 440 0025 PH: Machine Screw, Round, #4-40 x 1/4, Nylon, Philips panhead; Manufacturer: B&F Fastener Supply; CompType: Hardware; SymbolCreator: codlsc; U/M: EA
Logo1 = TI_Logo: Texas Instrument Corporate Signature; SymbolCreator: codlsc
Logo2 = Pb-Free: SymbolCreator: a0412235
ZZ1 = AssemblyNoteLabel: SymbolCreator: a0412235
ZZ2-ZZ4 = AssemblyNote: SymbolCreator: codlsc

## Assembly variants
001: not fitted FID1 FID2 FID3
